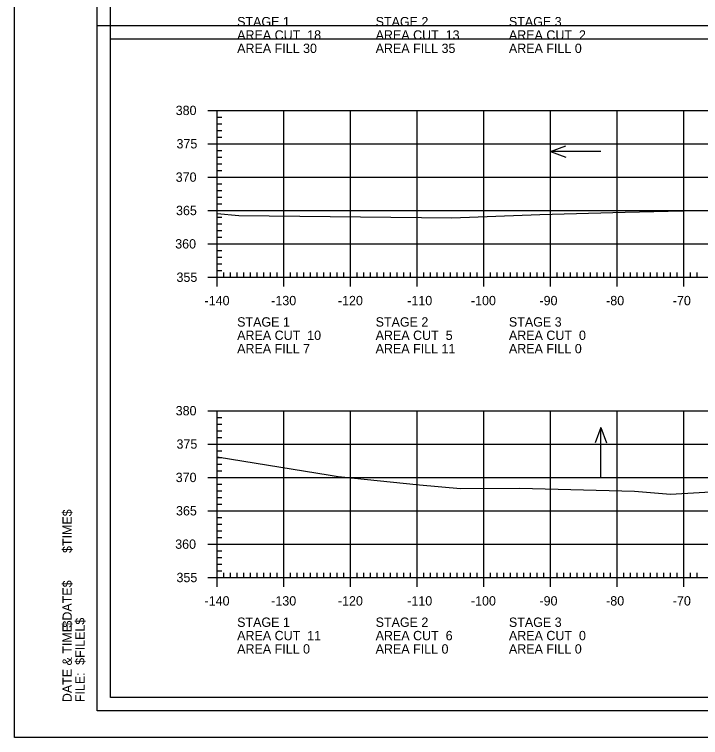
# Model space of a CAD drawing. Extents: x 1368910 to 1369601, y 380116 to 380950.
# Drawn here: x 1368909.8 to 1369012.7, y 380310.4 to 380418.8 of the extents above; entities that cross this region are included whole.
import ezdxf

# ---------------------------------------------------------------- set-up
doc = ezdxf.new("R2010")
doc.units = 0
for name, color, linetype in [('R_Axis', 7, 'Continuous'), ('R_Axis Annot', 7, 'Continuous'), ('R_Border', 7, 'Continuous'), ('R_Border Notes', 7, 'Continuous'), ('R_Border Plan-Plan', 7, 'Continuous'), ('R_Exist Surface', 7, 'Continuous'), ('R_Grid', 7, 'Continuous'), ('R_No Plot', 7, 'Continuous'), ('R_Water Annot', 7, 'Continuous')]:
    doc.layers.add(name, color=color, linetype=linetype)

msp = doc.modelspace()

# ---------------------------------------------------------------- linework, layer by layer
at = {"layer": 'R_Axis'}
for p, q in [((1368938.84, 380404.42), (1368941.64, 380404.42)), ((1368940.24, 380379.42), (1368940.24, 380404.42)), ((1368940.24, 380403.42), (1368940.94, 380403.42)), ((1368940.24, 380402.42), (1368940.94, 380402.42)), ((1368940.24, 380401.42), (1368940.94, 380401.42)), ((1368940.24, 380400.42), (1368940.94, 380400.42)), ((1368938.84, 380399.42), (1368941.64, 380399.42)), ((1368940.24, 380398.42), (1368940.94, 380398.42)), ((1368940.24, 380397.42), (1368940.94, 380397.42)), ((1368940.24, 380396.42), (1368940.94, 380396.42)), ((1368940.24, 380395.42), (1368940.94, 380395.42)), ((1368938.84, 380394.42), (1368941.64, 380394.42)), ((1368940.24, 380393.42), (1368940.94, 380393.42)), ((1368940.24, 380392.42), (1368940.94, 380392.42)), ((1368940.24, 380391.42), (1368940.94, 380391.42)), ((1368940.24, 380390.42), (1368940.94, 380390.42)), ((1368938.84, 380389.42), (1368941.64, 380389.42)), ((1368940.24, 380388.42), (1368940.94, 380388.42)), ((1368940.24, 380387.42), (1368940.94, 380387.42)), ((1368940.24, 380386.42), (1368940.94, 380386.42)), ((1368940.24, 380385.42), (1368940.94, 380385.42)), ((1368938.84, 380384.42), (1368941.64, 380384.42)), ((1368940.24, 380383.42), (1368940.94, 380383.42)), ((1368940.24, 380382.42), (1368940.94, 380382.42)), ((1368940.24, 380381.42), (1368940.94, 380381.42)), ((1368940.24, 380378.02), (1368940.24, 380380.82)), ((1368940.24, 380380.42), (1368940.94, 380380.42)), ((1368950.24, 380378.02), (1368950.24, 380380.82)), ((1368960.24, 380378.02), (1368960.24, 380380.82)), ((1368970.24, 380378.02), (1368970.24, 380380.82)), ((1368980.24, 380378.02), (1368980.24, 380380.82)), ((1368990.24, 380378.02), (1368990.24, 380380.82)), ((1369000.24, 380378.02), (1369000.24, 380380.82)), ((1369010.24, 380378.02), (1369010.24, 380380.82)), ((1368938.84, 380379.42), (1368941.64, 380379.42)), ((1368940.24, 380379.42), (1369220.24, 380379.42)), ((1368941.24, 380379.42), (1368941.24, 380380.12)), ((1368942.24, 380379.42), (1368942.24, 380380.12)), ((1368943.24, 380379.42), (1368943.24, 380380.12)), ((1368944.24, 380379.42), (1368944.24, 380380.12)), ((1368945.24, 380379.42), (1368945.24, 380380.12)), ((1368946.24, 380379.42), (1368946.24, 380380.12)), ((1368947.24, 380379.42), (1368947.24, 380380.12)), ((1368948.24, 380379.42), (1368948.24, 380380.12)), ((1368949.24, 380379.42), (1368949.24, 380380.12)), ((1368951.24, 380379.42), (1368951.24, 380380.12)), ((1368952.24, 380379.42), (1368952.24, 380380.12)), ((1368953.24, 380379.42), (1368953.24, 380380.12)), ((1368954.24, 380379.42), (1368954.24, 380380.12)), ((1368955.24, 380379.42), (1368955.24, 380380.12)), ((1368956.24, 380379.42), (1368956.24, 380380.12)), ((1368957.24, 380379.42), (1368957.24, 380380.12)), ((1368958.24, 380379.42), (1368958.24, 380380.12)), ((1368959.24, 380379.42), (1368959.24, 380380.12)), ((1368961.24, 380379.42), (1368961.24, 380380.12)), ((1368962.24, 380379.42), (1368962.24, 380380.12)), ((1368963.24, 380379.42), (1368963.24, 380380.12)), ((1368964.24, 380379.42), (1368964.24, 380380.12)), ((1368965.24, 380379.42), (1368965.24, 380380.12)), ((1368966.24, 380379.42), (1368966.24, 380380.12)), ((1368967.24, 380379.42), (1368967.24, 380380.12)), ((1368968.24, 380379.42), (1368968.24, 380380.12)), ((1368969.24, 380379.42), (1368969.24, 380380.12)), ((1368971.24, 380379.42), (1368971.24, 380380.12)), ((1368972.24, 380379.42), (1368972.24, 380380.12)), ((1368973.24, 380379.42), (1368973.24, 380380.12)), ((1368974.24, 380379.42), (1368974.24, 380380.12)), ((1368975.24, 380379.42), (1368975.24, 380380.12)), ((1368976.24, 380379.42), (1368976.24, 380380.12)), ((1368977.24, 380379.42), (1368977.24, 380380.12)), ((1368978.24, 380379.42), (1368978.24, 380380.12)), ((1368979.24, 380379.42), (1368979.24, 380380.12)), ((1368981.24, 380379.42), (1368981.24, 380380.12)), ((1368982.24, 380379.42), (1368982.24, 380380.12)), ((1368983.24, 380379.42), (1368983.24, 380380.12)), ((1368984.24, 380379.42), (1368984.24, 380380.12)), ((1368985.24, 380379.42), (1368985.24, 380380.12)), ((1368986.24, 380379.42), (1368986.24, 380380.12)), ((1368987.24, 380379.42), (1368987.24, 380380.12)), ((1368988.24, 380379.42), (1368988.24, 380380.12)), ((1368989.24, 380379.42), (1368989.24, 380380.12)), ((1368991.24, 380379.42), (1368991.24, 380380.12)), ((1368992.24, 380379.42), (1368992.24, 380380.12)), ((1368993.24, 380379.42), (1368993.24, 380380.12)), ((1368994.24, 380379.42), (1368994.24, 380380.12)), ((1368995.24, 380379.42), (1368995.24, 380380.12)), ((1368996.24, 380379.42), (1368996.24, 380380.12)), ((1368997.24, 380379.42), (1368997.24, 380380.12)), ((1368998.24, 380379.42), (1368998.24, 380380.12)), ((1368999.24, 380379.42), (1368999.24, 380380.12)), ((1369001.24, 380379.42), (1369001.24, 380380.12)), ((1369002.24, 380379.42), (1369002.24, 380380.12)), ((1369003.24, 380379.42), (1369003.24, 380380.12)), ((1369004.24, 380379.42), (1369004.24, 380380.12)), ((1369005.24, 380379.42), (1369005.24, 380380.12)), ((1369006.24, 380379.42), (1369006.24, 380380.12)), ((1369007.24, 380379.42), (1369007.24, 380380.12)), ((1369008.24, 380379.42), (1369008.24, 380380.12)), ((1369009.24, 380379.42), (1369009.24, 380380.12)), ((1369011.24, 380379.42), (1369011.24, 380380.12)), ((1369012.24, 380379.42), (1369012.24, 380380.12)), ((1368938.84, 380359.42), (1368941.64, 380359.42)), ((1368940.24, 380334.42), (1368940.24, 380359.42)), ((1368940.24, 380358.42), (1368940.94, 380358.42)), ((1368940.24, 380357.42), (1368940.94, 380357.42)), ((1368940.24, 380356.42), (1368940.94, 380356.42)), ((1368940.24, 380355.42), (1368940.94, 380355.42)), ((1368938.84, 380354.42), (1368941.64, 380354.42)), ((1368940.24, 380353.42), (1368940.94, 380353.42)), ((1368940.24, 380352.42), (1368940.94, 380352.42)), ((1368940.24, 380351.42), (1368940.94, 380351.42)), ((1368940.24, 380350.42), (1368940.94, 380350.42)), ((1368938.84, 380349.42), (1368941.64, 380349.42)), ((1368940.24, 380348.42), (1368940.94, 380348.42)), ((1368940.24, 380347.42), (1368940.94, 380347.42)), ((1368940.24, 380346.42), (1368940.94, 380346.42)), ((1368938.84, 380344.42), (1368941.64, 380344.42)), ((1368940.24, 380345.42), (1368940.94, 380345.42)), ((1368940.24, 380343.42), (1368940.94, 380343.42)), ((1368940.24, 380342.42), (1368940.94, 380342.42)), ((1368940.24, 380341.42), (1368940.94, 380341.42)), ((1368940.24, 380340.42), (1368940.94, 380340.42)), ((1368938.84, 380339.42), (1368941.64, 380339.42)), ((1368940.24, 380338.42), (1368940.94, 380338.42)), ((1368940.24, 380337.42), (1368940.94, 380337.42)), ((1368940.24, 380336.42), (1368940.94, 380336.42)), ((1368940.24, 380333.02), (1368940.24, 380335.82)), ((1368950.24, 380333.02), (1368950.24, 380335.82)), ((1368960.24, 380333.02), (1368960.24, 380335.82)), ((1368970.24, 380333.02), (1368970.24, 380335.82)), ((1368980.24, 380333.02), (1368980.24, 380335.82)), ((1368990.24, 380333.02), (1368990.24, 380335.82)), ((1369000.24, 380333.02), (1369000.24, 380335.82)), ((1369010.24, 380333.02), (1369010.24, 380335.82)), ((1368940.24, 380335.42), (1368940.94, 380335.42)), ((1368941.24, 380334.42), (1368941.24, 380335.12)), ((1368942.24, 380334.42), (1368942.24, 380335.12)), ((1368943.24, 380334.42), (1368943.24, 380335.12)), ((1368944.24, 380334.42), (1368944.24, 380335.12)), ((1368945.24, 380334.42), (1368945.24, 380335.12)), ((1368946.24, 380334.42), (1368946.24, 380335.12)), ((1368947.24, 380334.42), (1368947.24, 380335.12)), ((1368948.24, 380334.42), (1368948.24, 380335.12)), ((1368949.24, 380334.42), (1368949.24, 380335.12)), ((1368951.24, 380334.42), (1368951.24, 380335.12)), ((1368952.24, 380334.42), (1368952.24, 380335.12)), ((1368953.24, 380334.42), (1368953.24, 380335.12)), ((1368954.24, 380334.42), (1368954.24, 380335.12)), ((1368955.24, 380334.42), (1368955.24, 380335.12)), ((1368956.24, 380334.42), (1368956.24, 380335.12)), ((1368957.24, 380334.42), (1368957.24, 380335.12)), ((1368958.24, 380334.42), (1368958.24, 380335.12)), ((1368959.24, 380334.42), (1368959.24, 380335.12)), ((1368961.24, 380334.42), (1368961.24, 380335.12)), ((1368962.24, 380334.42), (1368962.24, 380335.12)), ((1368963.24, 380334.42), (1368963.24, 380335.12)), ((1368964.24, 380334.42), (1368964.24, 380335.12)), ((1368965.24, 380334.42), (1368965.24, 380335.12)), ((1368966.24, 380334.42), (1368966.24, 380335.12)), ((1368967.24, 380334.42), (1368967.24, 380335.12)), ((1368968.24, 380334.42), (1368968.24, 380335.12)), ((1368969.24, 380334.42), (1368969.24, 380335.12)), ((1368971.24, 380334.42), (1368971.24, 380335.12)), ((1368972.24, 380334.42), (1368972.24, 380335.12)), ((1368973.24, 380334.42), (1368973.24, 380335.12)), ((1368974.24, 380334.42), (1368974.24, 380335.12)), ((1368975.24, 380334.42), (1368975.24, 380335.12)), ((1368976.24, 380334.42), (1368976.24, 380335.12)), ((1368977.24, 380334.42), (1368977.24, 380335.12)), ((1368978.24, 380334.42), (1368978.24, 380335.12)), ((1368979.24, 380334.42), (1368979.24, 380335.12)), ((1368981.24, 380334.42), (1368981.24, 380335.12)), ((1368982.24, 380334.42), (1368982.24, 380335.12)), ((1368983.24, 380334.42), (1368983.24, 380335.12)), ((1368984.24, 380334.42), (1368984.24, 380335.12)), ((1368985.24, 380334.42), (1368985.24, 380335.12)), ((1368986.24, 380334.42), (1368986.24, 380335.12)), ((1368987.24, 380334.42), (1368987.24, 380335.12)), ((1368988.24, 380334.42), (1368988.24, 380335.12)), ((1368989.24, 380334.42), (1368989.24, 380335.12)), ((1368991.24, 380334.42), (1368991.24, 380335.12)), ((1368992.24, 380334.42), (1368992.24, 380335.12)), ((1368993.24, 380334.42), (1368993.24, 380335.12)), ((1368994.24, 380334.42), (1368994.24, 380335.12)), ((1368995.24, 380334.42), (1368995.24, 380335.12)), ((1368996.24, 380334.42), (1368996.24, 380335.12)), ((1368997.24, 380334.42), (1368997.24, 380335.12)), ((1368998.24, 380334.42), (1368998.24, 380335.12)), ((1368999.24, 380334.42), (1368999.24, 380335.12)), ((1369001.24, 380334.42), (1369001.24, 380335.12)), ((1369002.24, 380334.42), (1369002.24, 380335.12)), ((1369003.24, 380334.42), (1369003.24, 380335.12)), ((1369004.24, 380334.42), (1369004.24, 380335.12)), ((1369005.24, 380334.42), (1369005.24, 380335.12)), ((1369006.24, 380334.42), (1369006.24, 380335.12)), ((1369007.24, 380334.42), (1369007.24, 380335.12)), ((1369008.24, 380334.42), (1369008.24, 380335.12)), ((1369009.24, 380334.42), (1369009.24, 380335.12)), ((1369011.24, 380334.42), (1369011.24, 380335.12)), ((1369012.24, 380334.42), (1369012.24, 380335.12)), ((1368938.84, 380334.42), (1368941.64, 380334.42)), ((1368940.24, 380334.42), (1369220.24, 380334.42))]:
    msp.add_line(p, q, dxfattribs=at)
at = {"layer": 'R_Border'}
for p, q in [((1368922.24, 380314.42), (1368922.24, 380519.88)), ((1368922.24, 380314.42), (1368922.24, 380314.42)), ((1369238.42, 380314.42), (1368922.24, 380314.42))]:
    msp.add_line(p, q, dxfattribs=at)
at = {"layer": 'R_Border Plan-Plan'}
msp.add_line((1368922.24, 380417.15), (1369238.42, 380417.15), dxfattribs=at)
at = {"layer": 'R_Exist Surface'}
for points in [[(1368940.24, 380388.97), (1368943.49, 380388.67), (1368975.46, 380388.34), (1368988.64, 380388.8), (1369001.46, 380389.16), (1369014.38, 380389.49)], [(1368940.24, 380352.52), (1368957.21, 380349.76), (1368958.39, 380349.58), (1368970.59, 380348.32), (1368976.76, 380347.75), (1368985.66, 380347.8), (1369002.84, 380347.37), (1369008.24, 380346.92), (1369023.75, 380347.79)]]:
    msp.add_lwpolyline(points, dxfattribs=at)
at = {"layer": 'R_Grid'}
for p, q in [((1368940.24, 380404.42), (1369220.24, 380404.42)), ((1368940.24, 380379.42), (1368940.24, 380404.42)), ((1368950.24, 380379.42), (1368950.24, 380404.42)), ((1368960.24, 380379.42), (1368960.24, 380404.42)), ((1368970.24, 380379.42), (1368970.24, 380404.42)), ((1368980.24, 380379.42), (1368980.24, 380404.42)), ((1368990.24, 380379.42), (1368990.24, 380404.42)), ((1369000.24, 380379.42), (1369000.24, 380404.42)), ((1369010.24, 380379.42), (1369010.24, 380404.42)), ((1368940.24, 380399.42), (1369220.24, 380399.42)), ((1368940.24, 380394.42), (1369220.24, 380394.42)), ((1368940.24, 380389.42), (1369220.24, 380389.42)), ((1368940.24, 380384.42), (1369220.24, 380384.42)), ((1368940.24, 380379.42), (1369220.24, 380379.42)), ((1368940.24, 380359.42), (1369220.24, 380359.42)), ((1368940.24, 380334.42), (1368940.24, 380359.42)), ((1368950.24, 380334.42), (1368950.24, 380359.42)), ((1368960.24, 380334.42), (1368960.24, 380359.42)), ((1368970.24, 380334.42), (1368970.24, 380359.42)), ((1368980.24, 380334.42), (1368980.24, 380359.42)), ((1368990.24, 380334.42), (1368990.24, 380359.42)), ((1369000.24, 380334.42), (1369000.24, 380359.42)), ((1369010.24, 380334.42), (1369010.24, 380359.42)), ((1368940.24, 380354.42), (1369220.24, 380354.42)), ((1368940.24, 380349.42), (1369220.24, 380349.42)), ((1368940.24, 380344.42), (1369220.24, 380344.42)), ((1368940.24, 380339.42), (1369220.24, 380339.42)), ((1368940.24, 380334.42), (1369220.24, 380334.42))]:
    msp.add_line(p, q, dxfattribs=at)
at = {"layer": 'R_No Plot'}
for points in [[(1368909.84, 380523.78), (1369243.18, 380523.78), (1369243.18, 380310.44), (1368909.84, 380310.44)], [(1368924.24, 380517.88), (1369173.78, 380517.88), (1369173.78, 380508), (1369191.32, 380508), (1369215.42, 380508), (1369215.42, 380485.67), (1369236.42, 380485.67), (1369236.42, 380316.42), (1368924.24, 380316.42)], [(1368924.24, 380415.15), (1369236.42, 380415.15), (1369236.42, 380316.42), (1368924.24, 380316.42)]]:
    msp.add_lwpolyline(points, close=True, dxfattribs=at)
at = {"layer": 'R_Water Annot'}
for p, q in [((1368990.24, 380398.26), (1368992.55, 380399.1)), ((1368997.78, 380398.26), (1368990.24, 380398.26)), ((1368990.24, 380398.26), (1368992.55, 380397.42)), ((1368997.78, 380356.9), (1368996.94, 380354.59)), ((1368997.78, 380349.36), (1368997.78, 380356.9)), ((1368997.78, 380356.9), (1368998.62, 380354.59))]:
    msp.add_line(p, q, dxfattribs=at)

# ---------------------------------------------------------------- texts
at = {"layer": 'R_Axis Annot'}
for s, p in [('STAGE 1', (1368943.24, 380417.02)), ('STAGE 2', (1368964.01, 380417.02)), ('STAGE 3', (1368984, 380417.02)), ('AREA CUT  18', (1368943.24, 380415.02)), ('AREA CUT  13', (1368964.01, 380415.02)), ('AREA CUT  2', (1368984, 380415.02)), ('AREA FILL 30', (1368943.24, 380413.02)), ('AREA FILL 35', (1368964.01, 380413.02)), ('AREA FILL 0', (1368984, 380413.02)), ('380', (1368934.02, 380403.72)), ('375', (1368934.14, 380398.72)), ('370', (1368934.02, 380393.72)), ('365', (1368934.07, 380388.72)), ('360', (1368933.95, 380383.72)), ('355', (1368934.14, 380378.72)), ('-140', (1368938.35, 380375.22)), ('-130', (1368948.35, 380375.22)), ('-120', (1368958.35, 380375.22)), ('-110', (1368968.75, 380375.22)), ('-100', (1368978.3, 380375.22)), ('-90', (1368988.58, 380375.22)), ('-80', (1368998.58, 380375.22)), ('-70', (1369008.58, 380375.22)), ('STAGE 1', (1368943.24, 380372.02)), ('STAGE 2', (1368964.01, 380372.02)), ('STAGE 3', (1368984, 380372.02)), ('AREA CUT  10', (1368943.24, 380370.02)), ('AREA CUT  5', (1368964.01, 380370.02)), ('AREA CUT  0', (1368984, 380370.02)), ('AREA FILL 7', (1368943.24, 380368.02)), ('AREA FILL 11', (1368964.01, 380368.02)), ('AREA FILL 0', (1368984, 380368.02)), ('380', (1368934.02, 380358.72)), ('375', (1368934.14, 380353.72)), ('370', (1368934.02, 380348.72)), ('365', (1368934.07, 380343.72)), ('360', (1368933.95, 380338.72)), ('355', (1368934.14, 380333.72)), ('-140', (1368938.35, 380330.22)), ('-130', (1368948.35, 380330.22)), ('-120', (1368958.35, 380330.22)), ('-110', (1368968.75, 380330.22)), ('-100', (1368978.3, 380330.22)), ('-90', (1368988.58, 380330.22)), ('-80', (1368998.58, 380330.22)), ('-70', (1369008.58, 380330.22)), ('STAGE 1', (1368943.24, 380327.02)), ('STAGE 2', (1368964.01, 380327.02)), ('STAGE 3', (1368984, 380327.02)), ('AREA CUT  11', (1368943.24, 380325.02)), ('AREA CUT  6', (1368964.01, 380325.02)), ('AREA CUT  0', (1368984, 380325.02)), ('AREA FILL 0', (1368943.24, 380323.02)), ('AREA FILL 0', (1368964.01, 380323.02)), ('AREA FILL 0', (1368984, 380323.02))]:
    msp.add_text(s, height=1.4, dxfattribs=at).set_placement(p)
at = {"layer": 'R_Border Notes'}
for s, height, p in [('$TIME$', 1.397, (1368918.44, 380338.09)), ('$DATE$', 1.397, (1368918.44, 380326.92)), ('$FILEL$', 1.397, (1368920.36, 380321.33)), ('DATE & TIME:', 1.3968, (1368918.44, 380315.74)), ('FILE: ', 1.397, (1368920.36, 380315.74))]:
    msp.add_text(s, height=height, rotation=90, dxfattribs=at).set_placement(p)

doc.saveas('drawing.dxf')
